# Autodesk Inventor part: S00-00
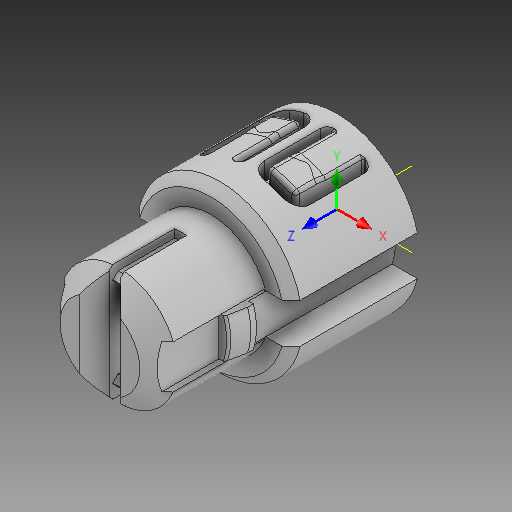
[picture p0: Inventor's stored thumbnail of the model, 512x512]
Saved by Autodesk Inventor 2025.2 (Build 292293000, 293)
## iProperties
Created: 2021-11
Part Number: S00-00
Material: PC/ABS plast
Document SubType Name: Modeling
Designer: Kadlčík Patrik
Density: 1.1 g/cm^3
Appearance: Hladká – bílá
Mass: 6.38765 g
Surface Area: 48.745 cm^2
Volume: 5.80695 cm^3
Description: Zadaný model
Sending System: Autodesk Translation Framework v10.10.0.1391
Preprocessor: ST-DEVELOPER v18.1
Title: G:/#Photo FIles/Inkscape Stuffs/mk4 Blenddoor Tab v4.step
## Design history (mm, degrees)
feature "Body1"
feature "Odstranit plochu1"
node "Těleso1"
other parameters: "d21" = 0, "d22" = 0, "d23" = 0, "d24" = 0, "d25" = 0, "d26" = 0
